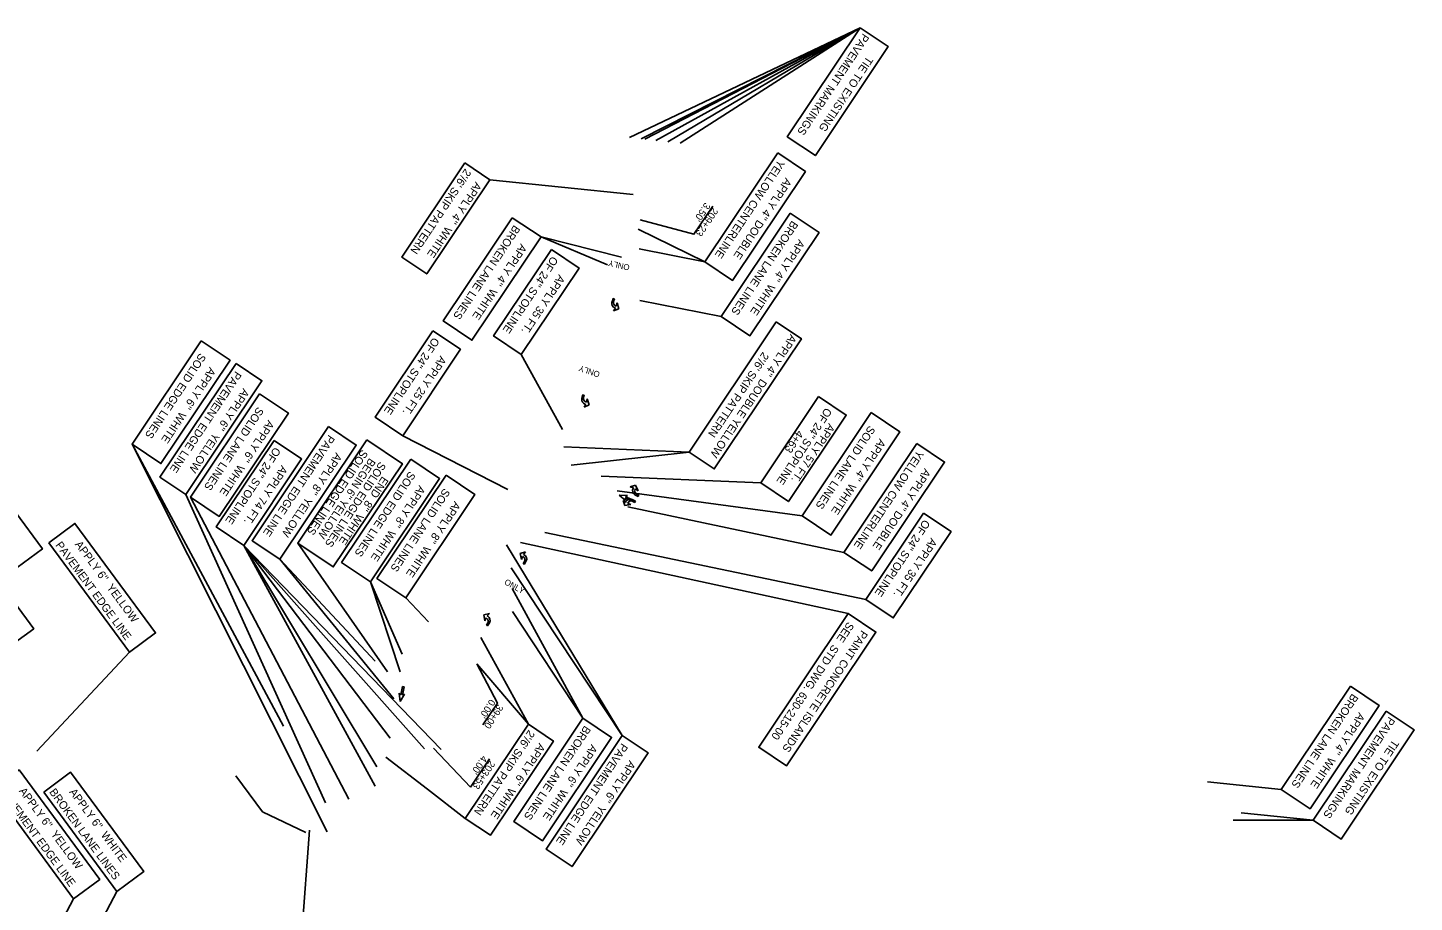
# Model space of a CAD drawing. Extents: x 1966013 to 1974896, y 789499 to 804826.
# Drawn here: x 1971229 to 1972615, y 796102 to 796976 of the extents above; entities that cross this region are included whole.
import ezdxf

# ---------------------------------------------------------------- set-up
doc = ezdxf.new("R2010")
doc.units = 0
doc.layers.add('RD_EX_H2O_BlueLn', color=7, linetype='Continuous')
doc.layers.add('RD_HC_TX_Rel_Sta50', color=7, linetype='Continuous')

msp = doc.modelspace()

# ---------------------------------------------------------------- linework, layer by layer
at = {"layer": 'RD_EX_H2O_BlueLn'}
for p, q in [((1972061.2, 796976), (1971830.5, 796866.3)), ((1972061.2, 796976), (1971842.1, 796864.9)), ((1972061.2, 796976), (1971845.8, 796864.5)), ((1972061.2, 796976), (1971856.8, 796863.3)), ((1972061.2, 796976), (1971868.9, 796862)), ((1972061.2, 796976), (1971881.3, 796860.7)), ((1971690.9, 796824.1), (1971834.4, 796809.3)), ((1971839.4, 796774.7), (1971905.9, 796742.2)), ((1971742.2, 796767), (1971808.7, 796739)), ((1971742.2, 796767), (1971822.7, 796746.6)), ((1971840.3, 796755), (1971905.9, 796742.2)), ((1971840.8, 796703.5), (1971922.3, 796687.6)), ((1971722.4, 796649.5), (1971763.7, 796574.5)), ((1971603.8, 796568.4), (1971709, 796514.6)), ((1971333.3, 796559.8), (1971528.4, 796172.7)), ((1971333.3, 796559.8), (1971484.8, 796278.3)), ((1971764.8, 796557.4), (1971890.2, 796552)), ((1971772.1, 796539), (1971890.2, 796552)), ((1971802.4, 796527.9), (1971961.8, 796521.2)), ((1971387, 796509.7), (1971526.5, 796201.6)), ((1971818.1, 796513.4), (1972003.1, 796488.3)), ((1971391.7, 796507), (1971550, 796205.1)), ((1971828.9, 796497.2), (1972045, 796451.8)), ((1971746, 796471.5), (1972066.7, 796404.8)), ((1971445, 796458.8), (1971591.3, 796266.1)), ((1971445, 796458.8), (1971577.9, 796237.4)), ((1971445, 796458.8), (1971625.7, 796255.5)), ((1971445, 796458.8), (1971576.2, 796218.3)), ((1971445, 796458.8), (1971642.2, 796254.7)), ((1971498.9, 796461), (1971588.6, 796332.5)), ((1971707.5, 796459.4), (1971823.4, 796268.8)), ((1971721.6, 796461.8), (1972049.3, 796390.7)), ((1971481, 796444.9), (1971576.3, 796343.1)), ((1971481, 796444.9), (1971594.8, 796305.5)), ((1971712.3, 796436.2), (1971823.4, 796268.8)), ((1971571.6, 796422.5), (1971603.4, 796350.2)), ((1971571.6, 796422.5), (1971601.4, 796332.3)), ((1971713.3, 796415.7), (1971784, 796286.1)), ((1971606.8, 796406.5), (1971629.7, 796382.5)), ((1971713.5, 796392.8), (1971784, 796286.1)), ((1971682.1, 796366.8), (1971729.5, 796280)), ((1971238, 796253.3), (1971330.6, 796352.1)), ((1971677.8, 796340.3), (1971729.5, 796280)), ((1971628.5, 796215.1), (1971586.9, 796247.2)), ((1972408.5, 796222.5), (1972482.2, 796214.9)), ((1971666.4, 796185.9), (1971628.5, 796215.1)), ((1972442.2, 796191.7), (1972514.1, 796184.3)), ((1972434.1, 796184.2), (1972514.1, 796184.3)), ((1971510.5, 796174.4), (1971499.1, 796017.7)), ((1971297.7, 796074.5), (1971318, 796113.1)), ((1971261.7, 796081), (1971274.7, 796105.7))]:
    msp.add_line(p, q, dxfattribs=at)
for points in [[(1972061.2, 796976), (1971988.3, 796867), (1972016.4, 796848.2), (1972089.3, 796957.2)], [(1971978.8, 796850.9), (1971905.9, 796742.2), (1971933.7, 796723.6), (1972006.5, 796832.3)], [(1971665.9, 796840.9), (1971602.8, 796746.8), (1971627.9, 796730), (1971690.9, 796824.1)], [(1971991.3, 796790.7), (1971922.2, 796687.5), (1971951, 796668.3), (1972020.1, 796771.4)], [(1971713.4, 796786.2), (1971644.3, 796683.1), (1971673.1, 796663.8), (1971742.2, 796767)], [(1971752.5, 796754.3), (1971694.7, 796668), (1971722.4, 796649.5), (1971780.2, 796735.8)], [(1971977.3, 796682), (1971890.2, 796552), (1971915.3, 796535.2), (1972002.4, 796665.2)], [(1971402.4, 796663), (1971333.3, 796559.8), (1971362.1, 796540.5), (1971431.2, 796643.7)], [(1971633.9, 796673.2), (1971576.2, 796586.9), (1971603.8, 796568.4), (1971661.6, 796654.7)], [(1971437.2, 796640.6), (1971361.1, 796527), (1971387, 796509.7), (1971463.1, 796623.2)], [(1971460.8, 796610.2), (1971391.7, 796507), (1971420.5, 796487.8), (1971489.6, 796590.9)], [(1972019.6, 796607.5), (1971961.8, 796521.2), (1971989.4, 796502.6), (1972047.2, 796589)], [(1972072.2, 796591.5), (1972003.1, 796488.3), (1972031.9, 796469.1), (1972101, 796572.2)], [(1971137.4, 796546.8), (1971218.5, 796436.7), (1971243.6, 796455.2), (1971162.5, 796565.2)], [(1971529.6, 796577.6), (1971453.2, 796463.5), (1971481, 796444.9), (1971557.4, 796559)], [(1971475.2, 796563.6), (1971417.4, 796477.3), (1971445, 796458.8), (1971502.8, 796545.1)], [(1971568, 796564.1), (1971498.9, 796461), (1971534.4, 796437.2), (1971603.5, 796540.4)], [(1972117.8, 796560.5), (1972045, 796451.8), (1972072.7, 796433.3), (1972145.6, 796542)], [(1971611.9, 796544.9), (1971542.8, 796441.7), (1971571.6, 796422.5), (1971640.7, 796525.6)], [(1971647.2, 796529), (1971578.1, 796425.8), (1971606.8, 796406.5), (1971675.9, 796509.7)], [(1971128.7, 796467), (1971209.8, 796357), (1971234.9, 796375.5), (1971153.8, 796485.5)], [(1972124.4, 796491.1), (1972066.7, 796404.8), (1972094.3, 796386.3), (1972152.1, 796472.6)], [(1971249.9, 796461.5), (1971330.6, 796352.1), (1971356.8, 796371.4), (1971276.2, 796480.8)], [(1972049.3, 796390.7), (1971959.8, 796257.1), (1971987.6, 796238.6), (1972077, 796372.1)], [(1972551.3, 796318), (1972482.2, 796214.9), (1972511, 796195.6), (1972580.1, 796298.7)], [(1972587.1, 796293.2), (1972514.1, 796184.3), (1972542.2, 796165.4), (1972615.2, 796274.4)], [(1971729.5, 796280), (1971666.4, 796185.9), (1971691.5, 796169.2), (1971754.5, 796263.3)], [(1971784, 796286.1), (1971714.9, 796183), (1971743.7, 796163.7), (1971812.7, 796266.9)], [(1971823.4, 796268.8), (1971747.3, 796155.2), (1971773.2, 796137.9), (1971849.3, 796251.4)], [(1971194.1, 796215.1), (1971274.7, 796105.7), (1971301, 796125), (1971220.3, 796234.4)], [(1971244.9, 796212.2), (1971318, 796113.1), (1971344.9, 796132.9), (1971271.8, 796232.1)]]:
    msp.add_lwpolyline(points, close=True, dxfattribs=at)
for points in [[(1971841.4, 796783.9), (1971895, 796769.7), (1971913.8, 796797.8)], [(1971677.8, 796340.3), (1971698.6, 796301.2), (1971684.1, 796279.5)], [(1971634.7, 796256.2), (1971671.5, 796217.2)], [(1971690.6, 796245.6), (1971671.5, 796217.2)], [(1971507.1, 796171.9), (1971463.8, 796192.5), (1971437.1, 796228.6)]]:
    msp.add_lwpolyline(points, dxfattribs=at)
at = {"layer": 'RD_HC_TX_Rel_Sta50'}
for p, q in [((1971814.3, 796705.5), (1971813.1, 796702.1)), ((1971814.3, 796705.5), (1971813.1, 796702.1)), ((1971815.7, 796705), (1971814.3, 796705.5)), ((1971815.7, 796705), (1971814.3, 796705.5)), ((1971814.7, 796702.4), (1971815.7, 796705)), ((1971814.7, 796702.4), (1971815.7, 796705)), ((1971815.7, 796705), (1971815.7, 796705)), ((1971815.7, 796705), (1971815.7, 796705)), ((1971816.6, 796695.8), (1971814.7, 796693.1)), ((1971816.6, 796695.8), (1971814.7, 796693.1)), ((1971814.7, 796693.1), (1971819.8, 796695.3)), ((1971814.7, 796693.1), (1971819.8, 796695.3)), ((1971815.8, 796696.1), (1971816.6, 796695.8)), ((1971815.8, 796696.1), (1971816.6, 796695.8)), ((1971817.4, 796697.9), (1971816.6, 796698.2)), ((1971817.4, 796697.9), (1971816.6, 796698.2)), ((1971818.1, 796701.2), (1971817.4, 796697.9)), ((1971818.1, 796701.2), (1971817.4, 796697.9)), ((1971819.8, 796695.3), (1971818.1, 796701.2)), ((1971819.8, 796695.3), (1971818.1, 796701.2)), ((1971784, 796609.2), (1971783, 796605.7)), ((1971784, 796609.2), (1971783, 796605.7)), ((1971785.4, 796608.8), (1971784, 796609.2)), ((1971785.4, 796608.8), (1971784, 796609.2)), ((1971784.6, 796606.2), (1971785.4, 796608.8)), ((1971784.6, 796606.2), (1971785.4, 796608.8)), ((1971785.4, 796608.8), (1971785.4, 796608.8)), ((1971785.4, 796608.8), (1971785.4, 796608.8)), ((1971787, 796599.7), (1971785.2, 796596.9)), ((1971787, 796599.7), (1971785.2, 796596.9)), ((1971785.2, 796596.9), (1971790.2, 796599.3)), ((1971785.2, 796596.9), (1971790.2, 796599.3)), ((1971786.1, 796599.9), (1971787, 796599.7)), ((1971786.1, 796599.9), (1971787, 796599.7)), ((1971787.6, 796601.9), (1971786.8, 796602.1)), ((1971787.6, 796601.9), (1971786.8, 796602.1)), ((1971788.1, 796605.2), (1971787.6, 796601.9)), ((1971788.1, 796605.2), (1971787.6, 796601.9)), ((1971790.2, 796599.3), (1971788.1, 796605.2)), ((1971790.2, 796599.3), (1971788.1, 796605.2)), ((1971831.3, 796517.2), (1971836.5, 796519)), ((1971831.3, 796517.2), (1971836.5, 796519)), ((1971834.5, 796516.4), (1971831.3, 796517.2)), ((1971834.5, 796516.4), (1971831.3, 796517.2)), ((1971834.1, 796515.7), (1971834.5, 796516.4)), ((1971834.1, 796515.7), (1971834.5, 796516.4)), ((1971836.5, 796515.3), (1971836.1, 796514.6)), ((1971836.5, 796515.3), (1971836.1, 796514.6)), ((1971836.5, 796519), (1971839.2, 796513.4)), ((1971836.5, 796519), (1971839.2, 796513.4)), ((1971839.2, 796513.4), (1971836.5, 796515.3)), ((1971839.2, 796513.4), (1971836.5, 796515.3)), ((1971837.5, 796510.2), (1971839.9, 796508.9)), ((1971837.5, 796510.2), (1971839.9, 796508.9)), ((1971826.7, 796503.6), (1971820.2, 796509)), ((1971820.2, 796509), (1971828.7, 796508.5)), ((1971826.7, 796501.7), (1971824.2, 796503.8)), ((1971824.2, 796503.8), (1971825.9, 796498.5)), ((1971824.2, 796503.8), (1971825.9, 796498.5)), ((1971826.7, 796501.7), (1971824.2, 796503.8)), ((1971825.9, 796498.5), (1971831.9, 796499.8)), ((1971825.9, 796498.5), (1971831.9, 796499.8)), ((1971834, 796502.6), (1971826, 796505.8)), ((1971826, 796505.8), (1971826.7, 796503.6)), ((1971828.7, 796508.5), (1971826.6, 796507.3)), ((1971826.6, 796507.3), (1971834.6, 796504.1)), ((1971827, 796502.5), (1971826.7, 796501.7)), ((1971827, 796502.5), (1971826.7, 796501.7)), ((1971828.8, 796500.7), (1971829.1, 796501.5)), ((1971828.8, 796500.7), (1971829.1, 796501.5)), ((1971831.9, 796499.8), (1971828.8, 796500.7)), ((1971831.9, 796499.8), (1971828.8, 796500.7)), ((1971836.6, 796503.1), (1971833.3, 796504.7)), ((1971836.6, 796503.1), (1971833.3, 796504.7)), ((1971833.4, 796503), (1971836, 796501.8)), ((1971833.4, 796503), (1971836, 796501.8)), ((1971834.6, 796504.1), (1971834, 796502.6)), ((1971839.2, 796507.6), (1971836, 796509.4)), ((1971839.2, 796507.6), (1971836, 796509.4)), ((1971836, 796501.8), (1971836.6, 796503.1)), ((1971836, 796501.8), (1971836.6, 796503.1)), ((1971836, 796501.8), (1971836, 796501.8)), ((1971836, 796501.8), (1971836, 796501.8)), ((1971839.9, 796508.9), (1971839.2, 796507.6)), ((1971839.9, 796508.9), (1971839.2, 796507.6)), ((1971839.9, 796508.9), (1971839.9, 796508.9)), ((1971839.9, 796508.9), (1971839.9, 796508.9)), ((1971726.7, 796452.3), (1971721.4, 796450.7)), ((1971726.7, 796452.3), (1971721.4, 796450.7)), ((1971721.4, 796450.7), (1971722.5, 796444.6)), ((1971721.4, 796450.7), (1971722.5, 796444.6)), ((1971722.5, 796444.6), (1971723.5, 796447.8)), ((1971722.5, 796444.6), (1971723.5, 796447.8)), ((1971723.5, 796447.8), (1971724.3, 796447.4)), ((1971723.5, 796447.8), (1971724.3, 796447.4)), ((1971725.6, 796443), (1971724.4, 796440.5)), ((1971725.6, 796443), (1971724.4, 796440.5)), ((1971724.4, 796440.5), (1971724.4, 796440.5)), ((1971724.4, 796440.5), (1971725.7, 796439.9)), ((1971724.4, 796440.5), (1971724.4, 796440.5)), ((1971724.4, 796440.5), (1971725.7, 796439.9)), ((1971724.5, 796449.8), (1971726.7, 796452.3)), ((1971724.5, 796449.8), (1971726.7, 796452.3)), ((1971725.3, 796449.4), (1971724.5, 796449.8)), ((1971725.3, 796449.4), (1971724.5, 796449.8)), ((1971725.7, 796439.9), (1971727.3, 796443.2)), ((1971725.7, 796439.9), (1971727.3, 796443.2)), ((1971690.5, 796390.6), (1971685.1, 796389.4)), ((1971690.5, 796390.6), (1971685.1, 796389.4)), ((1971685.1, 796389.4), (1971685.8, 796383.3)), ((1971685.1, 796389.4), (1971685.8, 796383.3)), ((1971685.8, 796383.3), (1971687, 796386.3)), ((1971685.8, 796383.3), (1971687, 796386.3)), ((1971687, 796386.3), (1971687.7, 796385.9)), ((1971687, 796386.3), (1971687.7, 796385.9)), ((1971688.2, 796388.3), (1971690.5, 796390.6)), ((1971688.2, 796388.3), (1971690.5, 796390.6)), ((1971688.9, 796387.9), (1971688.2, 796388.3)), ((1971688.9, 796387.9), (1971688.2, 796388.3)), ((1971688.8, 796381.5), (1971687.5, 796379.1)), ((1971688.8, 796381.5), (1971687.5, 796379.1)), ((1971687.5, 796379.1), (1971687.5, 796379.1)), ((1971687.5, 796379.1), (1971688.7, 796378.3)), ((1971687.5, 796379.1), (1971687.5, 796379.1)), ((1971687.5, 796379.1), (1971688.7, 796378.3)), ((1971688.7, 796378.3), (1971690.5, 796381.5)), ((1971688.7, 796378.3), (1971690.5, 796381.5)), ((1971601.9, 796309.4), (1971603.7, 796317.9)), ((1971605.3, 796317.5), (1971603.5, 796309.1)), ((1971603.7, 796317.9), (1971605.3, 796317.5)), ((1971601.3, 796302.8), (1971600.4, 796311.3)), ((1971600.4, 796311.3), (1971601.9, 796309.4)), ((1971605.6, 796310.2), (1971601.3, 796302.8)), ((1971603.5, 796309.1), (1971605.6, 796310.2))]:
    msp.add_line(p, q, dxfattribs=at)
for centre, radius, start, end in [((1971817.5, 796700.5), 4.72, 160.0121, 248.8547), ((1971817.5, 796700.5), 4.72, 160.0121, 248.8547), ((1971817.7, 796701.2), 3.18, 158.2876, 250.0504), ((1971817.7, 796701.2), 3.18, 158.2876, 250.0504), ((1971787.5, 796604.4), 4.72, 163.6432, 252.4857), ((1971787.5, 796604.4), 4.72, 163.6432, 252.4857), ((1971787.7, 796605.2), 3.18, 161.9186, 253.6814), ((1971787.7, 796605.2), 3.18, 161.9186, 253.6814), ((1971838.3, 796513.5), 4.72, 152.7679, 241.6105), ((1971838.3, 796513.5), 4.72, 152.7679, 241.6105), ((1971838.9, 796513.1), 3.18, 151.5723, 243.3351), ((1971838.9, 796513.1), 3.18, 151.5723, 243.3351), ((1971831.3, 796500.4), 4.72, 64.9167, 153.7592), ((1971831.3, 796500.4), 4.72, 64.9167, 153.7592), ((1971832, 796500.1), 3.18, 63.1921, 154.9549), ((1971832, 796500.1), 3.18, 63.1921, 154.9549), ((1971722.8, 796444.5), 3.18, 331.7967, 63.5596), ((1971722.8, 796444.5), 3.18, 331.7967, 63.5596), ((1971723.1, 796445.3), 4.72, 333.5213, 62.3639), ((1971723.1, 796445.3), 4.72, 333.5213, 62.3639), ((1971686.2, 796383.1), 3.18, 328.1657, 59.9285), ((1971686.2, 796383.1), 3.18, 328.1657, 59.9285), ((1971686.5, 796383.9), 4.72, 329.8903, 58.7329), ((1971686.5, 796383.9), 4.72, 329.8903, 58.7329)]:
    msp.add_arc(centre, radius, start, end, dxfattribs=at)

# ---------------------------------------------------------------- texts
at = {"layer": 'RD_EX_H2O_BlueLn'}
for s, height, rotation, p in [('PAVEMENT MARKINGS', 8, 236.1913, (1972064.1, 796970.9)), ('TIE TO EXISTING', 8, 236.1913, (1972068, 796948.1)), ("2'/6' SKIP PATTERN", 7.999, 236.1916, (1971666.3, 796835.8)), ('YELLOW CENTERLINE', 7.999, 236.1913, (1971979.6, 796844.7)), ("APPLY 4''  WHITE", 7.999, 236.1916, (1971676.7, 796822.6)), ("APPLY 4'' DOUBLE", 7.999, 236.1913, (1971986.7, 796826.6)), ("3.50'", 7, 236.1913, (1971906.2, 796801.9)), ('209+23', 7, 236.1913, (1971913.9, 796796.7)), ('BROKEN LANE LINES', 8, 236.1913, (1971715.2, 796779.4)), ('BROKEN LANE LINES', 8, 236.1913, (1971993.1, 796783.8)), ("APPLY 4''  WHITE", 8, 236.1913, (1971721.9, 796760.7)), ("APPLY 4''  WHITE", 8, 236.1913, (1971999.8, 796765.1)), ('OF 24" STOPLINE', 7.999, 236.1913, (1971753.1, 796748.3)), ('APPLY 35 FT.', 7.999, 236.1913, (1971760, 796729.9)), ('OF 24" STOPLINE', 7.999, 236.1913, (1971634.5, 796667.2)), ("APPLY 4''  DOUBLE YELLOW", 7.999, 236.1916, (1971991.6, 796670.3)), ('SOLID EDGE LINES', 8, 236.1913, (1971401.1, 796651.5)), ('APPLY 25 FT.', 7.999, 236.1913, (1971641.4, 796648.8)), ("2'/6' SKIP PATTERN", 7.999, 236.1916, (1971963.9, 796652.6)), ("APPLY 6''  WHITE", 8, 236.1913, (1971410.9, 796637.4)), ('PAVEMENT EDGE LINE', 8, 236.1914, (1971436.7, 796633.5)), ("APPLY 6''  YELLOW", 8, 236.1914, (1971444.4, 796616.2)), ('SOLID LANE LINES', 8, 236.1913, (1971458.8, 796597.7)), ('OF 24" STOPLINE', 7.999, 236.1913, (1972026.8, 796597)), ("APPLY 6''  WHITE", 8, 236.1913, (1971469.3, 796584.6)), ('APPLY 57 FT.', 7.999, 236.1913, (1972029.9, 796581.2)), ('PAVEMENT EDGE LINE', 8, 236.1914, (1971529.9, 796569.9)), ('4+63', 8, 236.1913, (1971998.6, 796574.6)), ('SOLID LANE LINES', 8, 236.1913, (1972070.2, 796579)), ("APPLY 4''  WHITE", 8, 236.1913, (1972080.7, 796565.9)), ('OF 24" STOPLINE', 7.999, 236.1913, (1971475.8, 796557.6)), ("APPLY 8''  YELLOW", 8, 236.1914, (1971537.1, 796552)), ('SOLID EDGE LINES', 8, 236.1913, (1971563, 796555.1)), ('YELLOW CENTERLINE', 7.999, 236.1913, (1972118.6, 796554.4)), ('APPLY 74 FT.', 7.999, 236.1913, (1971482.7, 796539.3)), ('BEGIN 6" YELLOW', 8, 236.1913, (1971570.7, 796546.6)), ('SOLID EDGE LINES', 8, 236.1913, (1971581, 796543)), ("END  8''  WHITE", 8, 236.1913, (1971583.5, 796528.3)), ('SOLID EDGE LINES', 8, 236.1913, (1971610.6, 796533.4)), ("APPLY 4'' DOUBLE", 7.999, 236.1913, (1972125.7, 796536.2)), ("APPLY 8''  WHITE", 8, 236.1913, (1971620.4, 796519.3)), ('SOLID LANE LINES', 8, 236.1913, (1971645.1, 796516.4)), ("APPLY 8''  WHITE", 8, 236.1913, (1971655.7, 796503.4)), ('OF 24" STOPLINE', 7.999, 236.1913, (1972125, 796485.2)), ('PAVEMENT EDGE LINE', 8, 306.3977, (1971256.3, 796459)), ("APPLY 6''  YELLOW", 8, 306.3977, (1971275.7, 796459.7)), ('APPLY 35 FT.', 7.999, 236.1913, (1972132, 796466.8)), ('SEE  STD DWG. 630-215-00', 7.999, 236.1913, (1972049, 796383)), ('PAINT CONCRETE ISLANDS', 7.999, 236.1913, (1972062.7, 796374.6)), ("0.00'", 7, 237.1913, (1971691.2, 796305.7)), ('BROKEN LANE LINES', 8, 236.1913, (1972553.1, 796311.2)), ('39+00', 7, 237.1913, (1971699, 796300.6)), ("APPLY 4''  WHITE", 8, 236.1913, (1972559.8, 796292.4)), ("2'/6' SKIP PATTERN", 7.999, 236.1916, (1971729.9, 796275)), ('BROKEN LANE LINES', 8, 236.1913, (1971785.8, 796279.3)), ('PAVEMENT MARKINGS', 8, 236.1913, (1972589.9, 796288.2)), ("APPLY 6''  WHITE", 7.999, 236.1916, (1971740.3, 796261.8)), ("APPLY 6''  WHITE", 8, 236.1913, (1971792.5, 796260.5)), ('PAVEMENT EDGE LINE', 8, 236.1914, (1971822.9, 796261.7)), ('TIE TO EXISTING', 8, 236.1913, (1972593.8, 796265.3)), ("4.00'", 7, 236.1913, (1971683.3, 796249.5)), ('203+53', 7, 236.1913, (1971691, 796244.4)), ("APPLY 6''  YELLOW", 8, 236.1914, (1971830.6, 796244.4)), ('PAVEMENT EDGE LINE', 8, 306.3977, (1971200.5, 796212.6)), ("APPLY 6''  YELLOW", 8, 306.3977, (1971219.8, 796213.3)), ('BROKEN LANE LINES', 8, 306.3977, (1971250.1, 796212.3)), ("APPLY 6''  WHITE", 8, 306.3977, (1971270, 796212.3))]:
    msp.add_text(s, height=height, rotation=rotation, dxfattribs=at).set_placement(p)
at = {"layer": 'RD_HC_TX_Rel_Sta50'}
for rotation, p in [(167.2105, (1971831.2, 796739)), (161.3316, (1971801.5, 796632)), (331.2097, (1971704.8, 796420.4))]:
    msp.add_text('ONLY', height=5.91, rotation=rotation, dxfattribs=at).set_placement(p)

doc.saveas('drawing.dxf')
